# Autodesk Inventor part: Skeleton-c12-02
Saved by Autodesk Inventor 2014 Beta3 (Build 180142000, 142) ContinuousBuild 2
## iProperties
Created: 2011-01
Part Number: Skeleton-c12-02
Material: Generic
Document SubType Name: Modeling
Designer: Thom Tremblay
Density: 1 g/cm^3
Appearance: Generic
_SkeletonDoc: Frame Skeleton File
_Version: 15.0.0
Author: Thom Tremblay
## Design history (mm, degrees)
sketch "Reference Skeleton"
